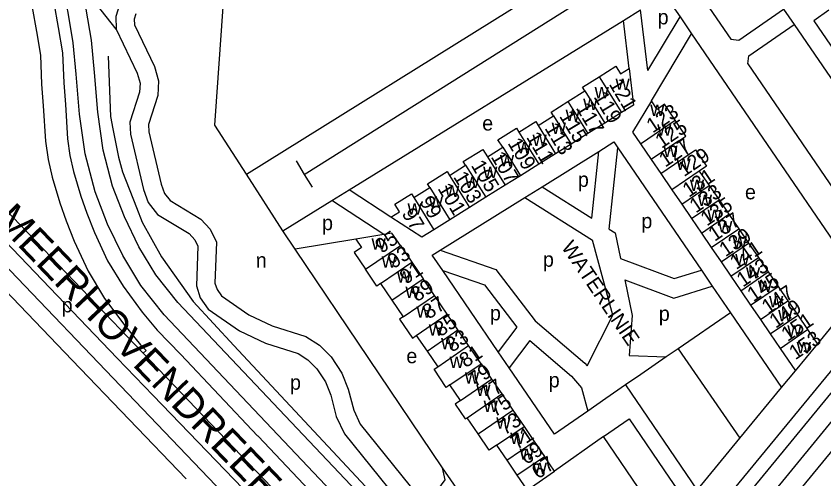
# Model space of a CAD drawing. Extents: x 154320 to 156262, y 382651 to 384180.
# Drawn here: x 155334.5 to 155553.7, y 382935.5 to 383061.1 of the extents above; entities that cross this region are included whole.
import ezdxf

# ---------------------------------------------------------------- set-up
doc = ezdxf.new("R2010")
doc.units = 0
for name, color, linetype in [('BLT_Basislijn', 7, 'Continuous'), ('BLT_Bebouwing', 7, 'Continuous'), ('BLT_Centroide', 7, 'Continuous'), ('BLT_Gemeentegrens', 7, 'Continuous'), ('BLT_Huisnummer', 7, 'Continuous'), ('BLT_Huisnummer_ tussenligend', 7, 'Continuous'), ('BLT_Onderverdeling_panden', 7, 'Continuous'), ('BLT_Straatnaam', 7, 'Continuous'), ('BLT_Straatnaam_hoofdweg', 7, 'Continuous'), ('BLT_Vlakafsluiter', 7, 'Continuous')]:
    doc.layers.add(name, color=color, linetype=linetype)

msp = doc.modelspace()

# ---------------------------------------------------------------- linework, layer by layer
at = {"layer": 'BLT_Basislijn'}
for p, q in [((155461.35, 383152.96), (155528.41, 383054.87)), ((155396.94, 383018.18), (155499.91, 383082.38)), ((155361.61, 383057.55), (155352.01, 383069.8)), ((155412.65, 383018.13), (155489.76, 383066.64)), ((155510.51, 383066.88), (155514.63, 383060.86)), ((155499.26, 383059.93), (155503.95, 383062.83)), ((155505.94, 383046.32), (155503.95, 383062.83)), ((155555.06, 383062.66), (155550.93, 383059.84)), ((155424.84, 383013.95), (155499.26, 383059.93)), ((155500.83, 383046.9), (155499.26, 383059.93)), ((155505.94, 383046.32), (155514.63, 383060.86)), ((155514.63, 383060.86), (155517.73, 383056.31)), ((155550.93, 383059.84), (155584.13, 383011.26)), ((155545.57, 383058.83), (155580.83, 383007.24)), ((155286.62, 383055.44), (155368.92, 382969.61)), ((155506.85, 383038.08), (155517.73, 383056.31)), ((155517.73, 383056.31), (155564.68, 382987.63)), ((155282.24, 383051.34), (155361.88, 382968.28)), ((155533.04, 383048.1), (155569.98, 382994.07)), ((155477.19, 383014.79), (155492.61, 383024.4)), ((155490.7, 383006.29), (155492.61, 383024.4)), ((155495.42, 383003.32), (155497.74, 383025.37)), ((155497.74, 383025.37), (155520.45, 382992.12)), ((155410.43, 383021.81), (155412.65, 383018.13)), ((155406.85, 383002.83), (155396.94, 383018.18)), ((155412.65, 383018.13), (155414.84, 383014.72)), ((155420.14, 383011.04), (155424.84, 383013.95)), ((155436.18, 383006.57), (155424.84, 383013.95)), ((155472.47, 383011.85), (155477.19, 383014.79)), ((155477.19, 383014.79), (155490.7, 383006.29)), ((155406.85, 383002.83), (155420.14, 383011.04)), ((155434.24, 383001.86), (155420.14, 383011.04)), ((155449.57, 382997.57), (155472.47, 383011.85)), ((155472.47, 383011.85), (155490.9, 383000.26)), ((155410.22, 382997.84), (155406.85, 383002.83)), ((155426.62, 383000.59), (155410.22, 382997.84)), ((155496.42, 382979.97), (155490.9, 383000.26)), ((155450.14, 382938.57), (155410.22, 382997.84)), ((155465.3, 382970.01), (155450.24, 382992.05)), ((155520.45, 382992.12), (155523.4, 382987.79)), ((155523.4, 382987.79), (155528.3, 382980.62)), ((155551.92, 382972.12), (155564.68, 382987.63)), ((155528.3, 382980.62), (155514.12, 382970.85)), ((155528.3, 382980.62), (155542.2, 382960.32)), ((155489.43, 382966.17), (155496.42, 382979.97)), ((155470.36, 382976.71), (155465.3, 382970.01)), ((155571.04, 382977.72), (155493.33, 382883.01)), ((155490.16, 382885.35), (155564.44, 382975.53)), ((155575.3, 382975.04), (155497.24, 382879.9)), ((155473.89, 382973.1), (155468.28, 382965.65)), ((155468.28, 382965.65), (155465.3, 382970.01)), ((155514.12, 382970.85), (155510.9, 382968.63)), ((155514.12, 382970.85), (155530.86, 382946.57)), ((155361.88, 382968.28), (155371.68, 382958.14)), ((155400, 382947.24), (155379.16, 382969.24)), ((155510.9, 382968.63), (155503.99, 382963.87)), ((155501, 382876.48), (155575.24, 382966.64)), ((155503.99, 382963.87), (155499.84, 382961.01)), ((155542.2, 382960.32), (155545.95, 382964.87)), ((155499.84, 382961.01), (155494.53, 382957.34)), ((155499.84, 382961.01), (155519.27, 382932.51)), ((155530.86, 382946.57), (155542.2, 382960.32)), ((155371.68, 382958.14), (155400, 382928.83)), ((155494.53, 382957.34), (155489.6, 382953.94)), ((155400.12, 382947.12), (155400, 382947.24)), ((155493.82, 382947.01), (155480.59, 382937.6)), ((155519.27, 382932.51), (155530.86, 382946.57))]:
    msp.add_line(p, q, dxfattribs=at)
for points in [[(155452.48, 382890.34), (155451.08, 382897.36), (155450.16, 382900.07), (155449.01, 382901.52), (155440.46, 382910.55), (155426.53, 382925.2), (155374.6, 382980.08), (155368.26, 382988), (155363.39, 382996.14), (155359.25, 383004.63), (155355.88, 383013.44), (155353.21, 383023.73), (155351.64, 383034.45), (155350.76, 383045.31), (155349.91, 383053.88), (155348.58, 383062.03), (155347.18, 383068.49), (155343.2, 383080.69), (155338.57, 383091.19), (155333.17, 383101.45)], [(155379.23, 383100.24), (155372.74, 383072.51), (155371.87, 383070.86), (155370.76, 383069.77), (155367.42, 383068.36), (155364.55, 383066.54), (155362.48, 383064.18), (155361.51, 383060.95), (155361.61, 383057.55)], [(155330.08, 383098.33), (155331.28, 383096.3), (155334.86, 383089.89), (155338.43, 383083.19), (155342.6, 383072.61), (155344.69, 383064.71), (155345.88, 383058), (155347.07, 383051.15), (155347.37, 383042.95), (155347.82, 383037.14), (155348.42, 383027.75), (155349.01, 383023.28), (155350.05, 383018.96), (155351.99, 383012.26), (155353.63, 383007.64), (155355.71, 383002.42)], [(155396.94, 383018.18), (155388.34, 383031.51), (155393.08, 383098.3)], [(155325.72, 383093.92), (155326.08, 383093.31), (155329.59, 383087.02), (155332.98, 383080.67), (155336.89, 383070.73), (155338.83, 383063.42), (155339.97, 383056.96), (155341.09, 383050.52), (155341.38, 383042.61), (155341.83, 383036.72), (155342.44, 383027.17), (155343.11, 383022.18), (155344.25, 383017.42), (155346.28, 383010.42), (155348.01, 383005.52), (155350.2, 383000.05)], [(155464.6, 382892.33), (155444.09, 382913.99), (155430.16, 382928.64), (155378.37, 382983.36), (155372.37, 382990.86), (155367.79, 382998.53), (155363.84, 383006.62), (155360.65, 383014.97), (155358.12, 383024.73), (155356.61, 383035.02), (155355.74, 383045.76), (155354.87, 383054.53), (155353.49, 383062.96), (155352.01, 383069.8)], [(155366.96, 383061.7), (155366.53, 383060.29), (155366.58, 383058.75), (155371.98, 383047.39), (155373.12, 383043.49), (155372.9, 383039.54), (155370.36, 383031.65), (155370.46, 383029.73), (155373.82, 383015.46), (155374.72, 383012.98), (155376.23, 383011.03), (155384.54, 383006.01), (155387.1, 383003.31), (155388.85, 382999.77), (155388.41, 382988.59), (155388.97, 382986.9), (155390.15, 382985.16), (155397.62, 382980.08), (155403.95, 382977.04), (155413.11, 382974.12), (155416.79, 382971.77), (155419.96, 382968.62), (155422.89, 382964.22), (155424.59, 382959.83), (155426.07, 382954.19), (155427.83, 382950.42), (155441.42, 382933.55)], [(155528.41, 383054.87), (155530.56, 383054.52), (155542.74, 383062.95)], [(155361.61, 383057.55), (155367.29, 383045.6), (155368.08, 383042.91), (155367.94, 383040.46), (155365.32, 383032.31), (155365.49, 383029.02), (155369.02, 383014.02), (155370.29, 383010.54), (155372.85, 383007.23), (155381.38, 383002.08), (155382.95, 383000.42), (155383.8, 382998.7), (155383.38, 382987.89), (155384.44, 382984.67), (155386.55, 382981.56), (155395.12, 382975.73), (155402.1, 382972.38), (155410.96, 382969.55), (155413.65, 382967.84), (155416.08, 382965.43), (155418.42, 382961.9), (155419.82, 382958.29), (155421.35, 382952.49), (155423.55, 382947.76), (155437.87, 382930)], [(155533.04, 383048.1), (155533.28, 383050.32), (155545.57, 383058.83)], [(155437.28, 382888.54), (155432.69, 382889.83), (155430.73, 382890.72), (155428.07, 382892.62), (155424.14, 382896.55), (155410.6, 382910.72), (155326.81, 382998.3), (155279.11, 383048.25)], [(155359.43, 383050.26), (155360.11, 383033.83), (155360.7, 383030.48), (155362.25, 383022.78), (155363.35, 383018.87), (155367.09, 383009.15), (155368.62, 383005.19), (155373.95, 382995.75), (155382.51, 382983.65), (155393.52, 382971.73), (155466.33, 382893.76)], [(155492.61, 383024.4), (155496.67, 383026.94), (155497.74, 383025.37)], [(155355.71, 383002.42), (155359.29, 382994.67), (155363.46, 382987.82), (155368.67, 382980.81), (155372.69, 382975.9), (155379.16, 382969.24)], [(155495.42, 383003.32), (155497.05, 383002.3), (155498.46, 382995.33)], [(155350.2, 383000.05), (155353.98, 382991.85), (155358.48, 382984.46), (155363.94, 382977.12), (155368.21, 382971.9), (155369.71, 382970.36)], [(155450.24, 382992.05), (155447.39, 382996.22), (155449.57, 382997.57)], [(155449.57, 382997.57), (155464.66, 382992.37), (155475.32, 382978.45), (155488.77, 382966.96), (155489.43, 382966.17)], [(155498.46, 382995.33), (155513.08, 382989.87), (155520.45, 382992.12)], [(155450.24, 382992.05), (155461.61, 382988.14), (155470.36, 382976.71)], [(155499.64, 382989.56), (155512.92, 382984.59), (155523.4, 382987.79)], [(155499.64, 382989.56), (155501.6, 382979.87), (155500.84, 382968.98), (155510.9, 382968.63)], [(155473.89, 382973.1), (155485.2, 382963.43), (155487.86, 382960.24), (155489.6, 382953.94)], [(155368.92, 382969.61), (155369.71, 382970.36)], [(155454.47, 382879.21), (155433.3, 382901.13), (155428.38, 382907.64), (155368.92, 382969.61)], [(155489.6, 382953.94), (155480.54, 382947.7), (155468.28, 382965.65)], [(155452.48, 382890.34), (155438.41, 382905.8), (155429.45, 382917.01), (155414.1, 382932.37), (155400.12, 382947.12)], [(155445.9, 382929.94), (155448.86, 382932.57), (155450.91, 382935.26), (155450.14, 382938.57)], [(155464.7, 382927.12), (155460.22, 382924.02), (155450.14, 382938.57)]]:
    msp.add_lwpolyline(points, dxfattribs=at)
at = {"layer": 'BLT_Bebouwing'}
for p, q in [((155500.83, 383046.9), (155502.04, 383036.94)), ((155484.22, 383037.92), (155488.8, 383040.78)), ((155506.85, 383038.08), (155501.76, 383029.57)), ((155476.11, 383031.45), (155480.27, 383034.04)), ((155498.77, 383034.91), (155494.22, 383032.07)), ((155494.22, 383032.07), (155489.64, 383029.22)), ((155489.64, 383029.22), (155485.06, 383026.36)), ((155485.06, 383026.36), (155480.88, 383023.75)), ((155503.9, 383026.43), (155506.82, 383022.17)), ((155514.28, 383027.23), (155516.87, 383023.45)), ((155462.36, 383022.9), (155466.5, 383025.49)), ((155480.88, 383023.75), (155476.29, 383020.89)), ((155506.82, 383022.17), (155509.42, 383018.35)), ((155452.05, 383017.89), (155456.44, 383020.64)), ((155476.29, 383020.89), (155471.32, 383017.79)), ((155471.32, 383017.79), (155467.18, 383015.21)), ((155509.42, 383018.35), (155512.41, 383013.97)), ((155519.87, 383019.06), (155522.54, 383015.14)), ((155442.37, 383011.85), (155446.77, 383014.6)), ((155467.18, 383015.21), (155461.91, 383011.93)), ((155512.41, 383013.97), (155515.09, 383010.06)), ((155522.54, 383015.14), (155525.21, 383011.23)), ((155461.91, 383011.93), (155457.5, 383009.18)), ((155525.21, 383011.23), (155527.88, 383007.32)), ((155457.5, 383009.18), (155452.18, 383005.86)), ((155515.09, 383010.06), (155517.76, 383006.14)), ((155444.56, 383001.11), (155436.18, 383006.57)), ((155527.88, 383007.32), (155530.55, 383003.41)), ((155452.18, 383005.86), (155447.81, 383003.14)), ((155517.76, 383006.14), (155520.43, 383002.23)), ((155436.44, 383002.22), (155434.24, 383001.86)), ((155520.43, 383002.23), (155523.1, 382998.32)), ((155530.55, 383003.41), (155533.22, 382999.5)), ((155434.24, 383001.86), (155426.62, 383000.59)), ((155438.74, 382998.85), (155441.85, 382994.31)), ((155523.1, 382998.32), (155525.77, 382994.41)), ((155533.22, 382999.5), (155535.9, 382995.59)), ((155535.9, 382995.59), (155538.57, 382991.68)), ((155441.85, 382994.31), (155444.92, 382989.81)), ((155525.77, 382994.41), (155528.45, 382990.5)), ((155538.57, 382991.68), (155541.24, 382987.76)), ((155447.99, 382985.31), (155444.92, 382989.81)), ((155528.45, 382990.5), (155531.12, 382986.59)), ((155433.38, 382988.54), (155436.45, 382984.04)), ((155541.24, 382987.76), (155543.91, 382983.85)), ((155451.46, 382980.23), (155447.99, 382985.31)), ((155531.12, 382986.59), (155533.79, 382982.68)), ((155436.45, 382984.04), (155439.51, 382979.54)), ((155533.79, 382982.68), (155536.46, 382978.76)), ((155543.91, 382983.85), (155546.58, 382979.94)), ((155454.37, 382975.98), (155451.46, 382980.23)), ((155536.46, 382978.76), (155539.13, 382974.85)), ((155546.58, 382979.94), (155549.25, 382976.03)), ((155457.27, 382971.73), (155454.37, 382975.98)), ((155549.25, 382976.03), (155551.92, 382972.12)), ((155443.05, 382974.42), (155445.98, 382970.19)), ((155539.13, 382974.85), (155541.8, 382970.94)), ((155460.69, 382966.72), (155457.27, 382971.73)), ((155545.95, 382964.87), (155551.92, 382972.12)), ((155445.98, 382970.19), (155448.9, 382965.95)), ((155541.8, 382970.94), (155545.95, 382964.87)), ((155460.69, 382966.72), (155463.5, 382962.61)), ((155455.05, 382956.84), (155452.19, 382961.02)), ((155463.5, 382962.61), (155466.25, 382958.59)), ((155466.25, 382958.59), (155469.27, 382954.16)), ((155469.27, 382954.16), (155472.3, 382949.73)), ((155459.84, 382947.72), (155456.82, 382952.14)), ((155472.3, 382949.73), (155475.06, 382945.69)), ((155475.06, 382945.69), (155477.82, 382941.64)), ((155464.85, 382944.64), (155467.61, 382940.59)), ((155467.61, 382940.6), (155470.37, 382936.55)), ((155473.13, 382932.51), (155480.59, 382937.6))]:
    msp.add_line(p, q, dxfattribs=at)
for points in [[(155492.7, 383044.64), (155497.24, 383047.47), (155498.5, 383045.42), (155500.83, 383046.9)], [(155488.8, 383040.78), (155488.16, 383041.81), (155492.7, 383044.64)], [(155480.27, 383034.04), (155479.63, 383035.07), (155484.22, 383037.92)], [(155513.31, 383032.86), (155510.38, 383037.16), (155508.41, 383035.79), (155506.85, 383038.08)], [(155502.04, 383036.94), (155498.77, 383034.91)], [(155514.28, 383027.23), (155516.25, 383028.56), (155513.31, 383032.86)], [(155466.5, 383025.49), (155465.22, 383027.52), (155470.25, 383030.66), (155470.88, 383029.64)], [(155470.88, 383029.64), (155475.47, 383032.49), (155476.11, 383031.45)], [(155501.76, 383029.57), (155503.9, 383026.43)], [(155456.44, 383020.64), (155455.8, 383021.65), (155461.09, 383024.93), (155462.36, 383022.9)], [(155516.87, 383023.45), (155518.84, 383024.8), (155521.84, 383020.4), (155519.87, 383019.06)], [(155446.77, 383014.6), (155446.14, 383015.62), (155451.42, 383018.9), (155452.05, 383017.89)], [(155436.18, 383006.57), (155438.52, 383008.03), (155437.25, 383010.08), (155441.74, 383012.87), (155442.37, 383011.85)], [(155438.74, 382998.85), (155436.44, 383002.22)], [(155447.81, 383003.14), (155444.56, 383001.11)], [(155426.62, 383000.59), (155428.17, 382998.32), (155426.18, 382996.96), (155429.28, 382992.41)], [(155433.38, 382988.54), (155432.38, 382987.86), (155429.28, 382992.41)], [(155439.51, 382979.54), (155438.53, 382978.86), (155442.07, 382973.74), (155443.05, 382974.42)], [(155452.19, 382961.02), (155451.19, 382960.35), (155447.9, 382965.26), (155448.9, 382965.95)], [(155455.05, 382956.84), (155453.57, 382955.82), (155456.32, 382951.8), (155456.82, 382952.14)], [(155493.82, 382947.01), (155500.85, 382951.81), (155511.82, 382935.73), (155516.39, 382929.02)], [(155464.85, 382944.64), (155462.87, 382943.29), (155459.84, 382947.72)], [(155497.76, 382906.34), (155491.19, 382911.74), (155505.78, 382929.47), (155504.79, 382930.92), (155493.82, 382947.01)], [(155480.59, 382937.6), (155477.82, 382941.64)], [(155470.37, 382936.55), (155473.13, 382932.51)]]:
    msp.add_lwpolyline(points, dxfattribs=at)
at = {"layer": 'BLT_Gemeentegrens'}
msp.add_line((155274.11, 383046.56), (155349.67, 382967.76), dxfattribs=at)
msp.add_lwpolyline([(155349.67, 382967.76), (155380.57, 382935.54)], dxfattribs=at)
at = {"layer": 'BLT_Onderverdeling_panden'}
for p, q in [((155492.7, 383044.64), (155498.77, 383034.91)), ((155488.8, 383040.78), (155494.22, 383032.07)), ((155484.22, 383037.92), (155489.64, 383029.22)), ((155480.27, 383034.04), (155485.06, 383026.36)), ((155503.9, 383026.43), (155513.31, 383032.86)), ((155476.11, 383031.45), (155480.88, 383023.75)), ((155470.88, 383029.64), (155476.29, 383020.89)), ((155514.28, 383027.23), (155506.82, 383022.17)), ((155466.5, 383025.49), (155471.32, 383017.79)), ((155462.36, 383022.9), (155467.18, 383015.21)), ((155509.42, 383018.35), (155516.87, 383023.45)), ((155456.44, 383020.64), (155461.91, 383011.93)), ((155452.05, 383017.89), (155457.5, 383009.18)), ((155519.87, 383019.06), (155512.41, 383013.97)), ((155446.77, 383014.6), (155452.18, 383005.86)), ((155515.09, 383010.06), (155522.54, 383015.14)), ((155442.37, 383011.85), (155447.81, 383003.14)), ((155517.76, 383006.14), (155525.21, 383011.23)), ((155520.43, 383002.23), (155527.88, 383007.32)), ((155523.1, 382998.32), (155530.55, 383003.41)), ((155429.28, 382992.41), (155438.74, 382998.85)), ((155525.77, 382994.41), (155533.22, 382999.5)), ((155528.45, 382990.5), (155535.9, 382995.59)), ((155433.38, 382988.54), (155441.85, 382994.31)), ((155531.12, 382986.59), (155538.57, 382991.68)), ((155436.45, 382984.04), (155444.92, 382989.81)), ((155533.79, 382982.68), (155541.24, 382987.76)), ((155439.51, 382979.54), (155447.99, 382985.31)), ((155536.46, 382978.76), (155543.91, 382983.85)), ((155443.05, 382974.42), (155451.46, 382980.23)), ((155539.13, 382974.85), (155546.58, 382979.94)), ((155445.98, 382970.19), (155454.37, 382975.98)), ((155541.8, 382970.94), (155549.25, 382976.03)), ((155448.9, 382965.95), (155457.27, 382971.73)), ((155452.19, 382961.02), (155460.69, 382966.72)), ((155455.05, 382956.84), (155463.5, 382962.61)), ((155456.82, 382952.14), (155466.25, 382958.59)), ((155459.84, 382947.72), (155469.27, 382954.16)), ((155464.85, 382944.64), (155472.3, 382949.73)), ((155467.61, 382940.6), (155475.06, 382945.69)), ((155470.37, 382936.55), (155477.82, 382941.64))]:
    msp.add_line(p, q, dxfattribs=at)
at = {"layer": 'BLT_Vlakafsluiter'}
msp.add_line((155542.74, 383062.95), (155545.57, 383058.83), dxfattribs=at)

# ---------------------------------------------------------------- texts
at = {"layer": 'BLT_Centroide'}
for s, p in [('p', (155508.55, 383058.85)), ('w', (155497.12, 383041.09)), ('w', (155491.45, 383038.77)), ('w', (155488.35, 383035.65)), ('w', (155483.58, 383032.65)), ('w', (155506.55, 383033.99)), ('e', (155460.95, 383030.05)), ('w', (155479.81, 383029.1)), ('w', (155508.43, 383028.66)), ('w', (155474.6, 383025.88)), ('w', (155470.38, 383023.88)), ('w', (155510.1, 383022.88)), ('w', (155465.74, 383020.35)), ('w', (155513.65, 383019.33)), ('w', (155461.19, 383017.13)), ('w', (155456.31, 383014.46)), ('p', (155486.91, 383014.76)), ('w', (155517.31, 383013.64)), ('w', (155450.87, 383012.02)), ('e', (155532.26, 383011.38)), ('w', (155446.44, 383009.13)), ('w', (155519.46, 383009.58)), ('w', (155440.67, 383007.25)), ('p', (155504.14, 383003.53)), ('w', (155522.06, 383005.52)), ('p', (155417.48, 383003.02)), ('w', (155524.98, 383002.41)), ('w', (155430.91, 382997.7)), ('w', (155528.91, 382998.16)), ('n', (155399.5, 382992.87)), ('w', (155433.68, 382992.81)), ('p', (155477.42, 382993.09)), ('w', (155529.6, 382993.51)), ('w', (155437.79, 382988.81)), ('w', (155532.52, 382989.9)), ('w', (155535.75, 382986.28)), ('w', (155440.11, 382984.59)), ('w', (155538.79, 382982.09)), ('p', (155346.81, 382980.71)), ('w', (155443.11, 382979.26)), ('p', (155463.03, 382978.54)), ('p', (155508.88, 382978.39)), ('w', (155541.26, 382978.29)), ('w', (155446.44, 382974.38)), ('w', (155543.74, 382974.16)), ('w', (155449.77, 382970.71)), ('w', (155546.29, 382969.56)), ('e', (155440.36, 382966.91)), ('w', (155452.1, 382965.6)), ('p', (155408.78, 382959.72)), ('w', (155456.23, 382961.36)), ('p', (155479, 382960.35)), ('w', (155459.33, 382958.03)), ('w', (155461.33, 382953.7)), ('w', (155464.77, 382949.14)), ('w', (155468.54, 382945.03)), ('w', (155471.09, 382940.7)), ('w', (155474.64, 382936.82))]:
    msp.add_text(s, height=4, dxfattribs=at).set_placement(p)
at = {"layer": 'BLT_Huisnummer'}
for s, rotation, p in [('121', 300.8685, (155495.21, 383042.65)), ('117', 300.8685, (155486.26, 383036.18)), ('123', 33.8685, (155507.22, 383029.22)), ('113', 300.8685, (155477.77, 383030.7)), ('109', 300.8685, (155467.74, 383026.62)), ('127', 33.8685, (155510.62, 383019.95)), ('105', 300.8685, (155457.79, 383020.59)), ('131', 33.8685, (155517.01, 383011.76)), ('101', 300.8685, (155448.75, 383014.33)), ('135', 33.8685, (155521.9, 383003.97)), ('97', 300.8685, (155438.99, 383007.54)), ('95', 33.8685, (155433.6, 382996.55)), ('139', 33.8685, (155526.97, 382995.63)), ('91', 33.8685, (155440.24, 382988.16)), ('143', 33.8685, (155531.69, 382987.42)), ('147', 33.8685, (155538.51, 382980.08)), ('87', 33.8685, (155446.42, 382978.7)), ('151', 33.8685, (155543.81, 382972.64)), ('83', 33.8685, (155452.75, 382969.74)), ('153', 33.8685, (155545.93, 382967.69)), ('79', 33.8685, (155458.89, 382960.36)), ('75', 33.8685, (155464.37, 382952.15)), ('71', 33.8685, (155470.35, 382943.31)), ('67', 33.8685, (155476.08, 382935.33))]:
    msp.add_text(s, height=4, rotation=rotation, dxfattribs=at).set_placement(p)
at = {"layer": 'BLT_Huisnummer_ tussenligend'}
for s, rotation, p in [('119', 300.8685, (155491.06, 383039.2)), ('115', 300.8685, (155481.74, 383033.96)), ('125', 33.8685, (155509.61, 383025.04)), ('111', 300.8685, (155472.79, 383028.26)), ('107', 300.8685, (155463.19, 383022.91)), ('129', 33.8685, (155515.72, 383017.38)), ('103', 301.8685, (155452.99, 383017.46)), ('133', 33.8685, (155518.91, 383007.5)), ('99', 300.8685, (155443.78, 383010.84)), ('137', 33.8685, (155524.02, 382999.82)), ('93', 33.8685, (155436.92, 382992.41)), ('141', 33.8685, (155529.87, 382992.16)), ('145', 33.8685, (155534.56, 382983.43)), ('89', 33.8685, (155443.24, 382983.41)), ('149', 33.8685, (155540.58, 382976.23)), ('85', 33.8685, (155449.6, 382973.95)), ('81', 33.8685, (155456.44, 382965.54)), ('77', 33.8685, (155462.05, 382956.33)), ('73', 33.8685, (155467.05, 382947.26)), ('69', 33.8685, (155472.91, 382939.23))]:
    msp.add_text(s, height=4, rotation=rotation, dxfattribs=at).set_placement(p)
at = {"layer": 'BLT_Straatnaam'}
msp.add_text('WATERLINIE', height=4, rotation=304.0883, dxfattribs=at).set_placement((155482.27, 382998.41))
at = {"layer": 'BLT_Straatnaam_hoofdweg'}
msp.add_text('MEERHOVENDREEF', height=8, rotation=313.7994, dxfattribs=at).set_placement((155328.39, 383005.47))

doc.saveas('drawing.dxf')
